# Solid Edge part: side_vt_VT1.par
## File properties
Author: haileyy
Template: ansi part.par
Last saved by: harmonj5
Revision: 7
Application: Solid Edge
Accuracy: 0.990
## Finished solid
Body 1: solid body, 19 faces, 51 edges, 34 vertices.
  Faces by surface: plane 15, swept 4
  Edges by curve: line 43, spline 8
Bounding box of the edges (mm; curved faces can reach further): 85.881 x 22.561 x 3.175, from (-216.0372, 111.6518, -3.175) to (-130.1558, 134.2126, 0).
Planar faces by outward normal: +x 5, +y 3, +z 1, -x 1, -y 3, -z 1, oblique 1
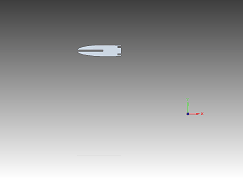
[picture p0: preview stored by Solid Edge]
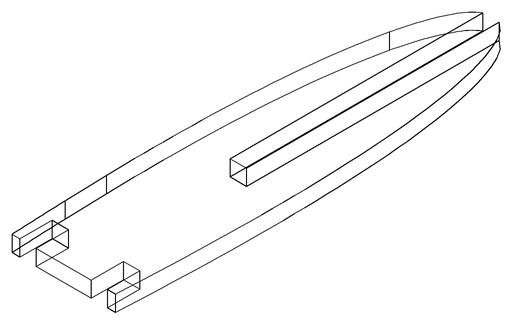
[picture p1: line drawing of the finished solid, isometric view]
